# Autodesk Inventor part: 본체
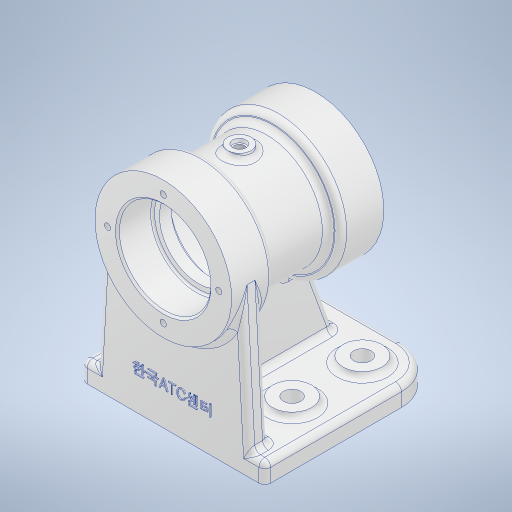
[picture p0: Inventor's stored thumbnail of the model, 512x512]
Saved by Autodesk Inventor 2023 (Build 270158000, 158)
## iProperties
Created: 2024-02
Part Number: 본체
Material: 알루미늄 6061
Document SubType Name: Modeling
Designer: home
Density: 2.7 g/cm^3
Appearance: 알루미늄 - 평지
Mass: 719.723 g
Surface Area: 647.2 cm^2
Volume: 266.564 cm^3
Author: home
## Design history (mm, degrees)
sketch "스케치1"
  geometry: L1 (-47, -5)-(47, -5); L2 (47, -5)-(47, 5); L3 (47, 5)-(-47, 5); L4 (-47, 5)-(-47, -5); L5 (-47, -5)-(47, 5); L6 (47, -5)-(-47, 5); 1 further point
  constraints: 12 end point, 2 midpoint, 2 parallel, 1 horizontal, 1 perpendicular
  dimensions: "d0" = 94 distance of L2.end L3.end; "d1" = 10 distance of L3.end L1.start
extrude "돌출1" new body sketch "스케치1" distance "d2" = 90; taper "d3" = 0 deg
node "작업 평면1"
sketch "스케치2"
  geometry: L1 (-47, -5)-(47, -5) reference; C1 r 35 at (0, 75); 1 further point
  constraints: 1 centre point, 1 vertical alignment
  dimensions: "d5" = 70 diameter of C1; "d6" = 80 distance from line of L1 C1.centre
extrude "돌출2" join sketch "스케치2" distance "d7" = 22; taper "d8" = 0 deg
sketch "스케치3"
  geometry: C1 r 35 at (0, 0) reference; C2 r 28.5 at (0, 0); 1 further point
  constraints: 1 centre point, 1 coincident
  dimensions: "d9" = 57 diameter of C2
extrude "돌출3" join sketch "스케치3" distance "d10" = 34; taper "d11" = 0 deg
sketch "스케치4"
  geometry: C1 r 28.5 at (0, 0) reference; C2 r 35 at (0, 0); 1 further point
  constraints: 1 centre point, 1 coincident
  dimensions: "d12" = 70 diameter of C2
extrude "돌출4" join sketch "스케치4" distance "d13" = 22; taper "d14" = 0 deg
sketch "스케치5"
  geometry: L1 (-47, 5)-(47, 5) reference; L2 (39, 5)-(34.945, 76.969); L3 (47, -5)-(47, 5) reference; L4 (0, 5)-(39, 5); L5 (34.945, 76.969)-(0, 56.544); L6 (0, 56.544)-(0, 5); 2 further points
  constraints: 8 end point, 1 collinear, 1 midpoint, 1 perpendicular, 1 point on line, 3 other
  dimensions: "d15" = 8 distance from line of L3 L2.start
extrude "돌출5" join sketch "스케치5" distance "d16" = 10; taper "d17" = 0 deg
sketch "스케치6"
  geometry: L1 (5, 0)-(5, -90) reference; L2 (5, -78)-(64.493, -56.346); L3 (64.493, -56.346)-(64.493, 0); L4 (5, 0)-(76.969, 0) reference; L5 (5, -90)-(-5, -90) reference; 2 further points
  constraints: 4 end point, 2 point on line, 1 coincident, 1 vertical
  dimensions: "d18" = 12 distance from line of L5 point (5, -78); "d19" = 70 deg angle of L2 L1
extrude "돌출6" join sketch "스케치6" stored distance "d20" = 10; taper "d21" = 0 deg
sketch "스케치7"
  geometry: L1 (40, -73)-(110, -73) reference; L2 (75, -73)-(75, 5); L3 (110, 5)-(40, 5) reference; L4 (110, 5)-(110, -17) reference; L5 (75, 5)-(98.5, 5); L6 (98.5, 5)-(98.5, -13); L7 (98.5, -13)-(75, -13); L8 (75, -13)-(75, 5); L9 (75, -13)-(95, -13); L10 (95, -13)-(95, -19); L11 (95, -19)-(75, -19); L12 (75, -19)-(75, -13); L13 (75, -19)-(98.5, -19); L14 (98.5, -19)-(98.5, -49); L15 (98.5, -49)-(75, -49); L16 (75, -49)-(75, -19); L17 (75, -49)-(95, -49); L18 (95, -49)-(95, -55); L19 (95, -55)-(75, -55); L20 (75, -55)-(75, -49); L21 (75, -55)-(98.5, -55); L22 (98.5, -55)-(98.5, -73); L23 (98.5, -73)-(75, -73); L24 (75, -73)-(75, -55); 6 further points
  constraints: 42 end point, 10 parallel, 5 horizontal, 5 perpendicular, 3 point on line, 2 midpoint
  dimensions: "d22" = 47 diameter of L6 L2; "d23" = 40 diameter of L10 L2; "d24" = 47 diameter of L14 L2; "d25" = 18 distance of L5.end L6.end; "d26" = 6 distance of L9.end L10.end; "d27" = 30 distance of L13.end L14.end; "d28" = 18 distance of L21.end L22.end
revolve "회전1" sketch "스케치7" stored, may be unused: angle "d29" = 90 deg
fillet "모깎기1" dims "d30" = 3
fillet "모깎기2" dims "d31" = 1
sketch "스케치8"
  geometry: C1 r 35 at (0, 0) reference; A1 r 28.5 centre (0, 0) between (-5, -28.058) and (5, -28.058); A2 r 28.5 centre (0, 0) between (5, -28.058) and (-5, -28.058) reference; 2 further points
  constraints: 1 centre point, 1 coincident, 1 point on circle
  dimensions: "d32" = 57 diameter of A1
hole "구멍1" sketch "스케치8" at (0, 28.5) diameter "d33" = 3.242; stored, may be unused: countersink angle "d37" = 90 deg, drill point angle "d39" = 118 deg; dims "d34" = 8, "d35" = 4, "d36" = 2, "d38" = 10
sketch "스케치9"
  geometry: C1 r 35 at (0, 0) reference; C2 r 28.5 at (0, 0); C3 r 1.621 at (0, 28.5) reference; 2 further points
  constraints: 2 coincident, 1 centre point
  dimensions: "d43" = 57 diameter of C2
hole "구멍2" sketch "스케치9" at (0, 28.5) diameter "d44" = 3.242; stored, may be unused: countersink angle "d48" = 90 deg, drill point angle "d50" = 118 deg; dims "d45" = 8, "d46" = 4, "d47" = 2, "d49" = 10
sketch "스케치10"
  geometry: L1 (8, -90)-(0, -90) reference; L2 (20, -20)-(74, -20); L3 (74, -20)-(74, -56); L4 (74, -56)-(20, -56); L5 (20, -56)-(20, -20); L6 (20, -20)-(74, -56); L7 (74, -20)-(20, -56); L8 (12, -90)-(82, -90) reference; C1 r 10 at (20, -20); C2 r 10 at (74, -20); C3 r 10 at (74, -56); C4 r 10 at (20, -56); 5 further points
  constraints: 12 end point, 4 centre point, 4 coincident, 3 midpoint, 2 parallel, 1 horizontal, 1 perpendicular, 1 vertical alignment
  dimensions: "d54" = 54 distance of L2.start L2.end; "d55" = 36 distance of L4.end L2.start; "d56" = 34 distance between parallel lines of L1 L4; "d57" = 20 diameter of C1; "d58" = 20 diameter of C2; "d59" = 20 diameter of C3; "d60" = 20 diameter of C4
extrude "돌출7" join sketch "스케치10" distance "d61" = 3; taper "d62" = 0 deg
sketch "스케치11"
  geometry: C1 r 10 at (0, 0) reference; C2 r 4.5 at (0, 0); 1 further point
  constraints: 1 centre point, 1 coincident
  dimensions: "d64" = 9 diameter of C2
extrude "돌출8" cut sketch "스케치11" extent not by distance; stored distance "d65" = 0; taper "d66" = 0 deg
sketch "스케치12"
  geometry: C1 r 10 at (0, 0) reference; C2 r 4.5 at (0, 0); 1 further point
  constraints: 1 centre point, 1 coincident
  dimensions: "d67" = 9 diameter of C2
extrude "돌출9" cut sketch "스케치12" extent not by distance; stored distance "d68" = 0; taper "d69" = 0 deg
fillet "모깎기3" dims "d70" = 20
fillet "모깎기4" dims "d71" = 3
fillet "모깎기5" dims "d72" = 3
fillet "모깎기6" dims "d73" = 3
fillet "모깎기7" dims "d74" = 3
fillet "모깎기8" dims "d75" = 3
node "작업 평면2"
sketch "스케치13"
  geometry: L1 (-3.489, 93)-(57.489, 93) reference; L2 (62, 95)-(-8, 95) reference; C1 r 6 at (27, 56); 2 further points
  constraints: 1 centre point, 1 midpoint, 1 vertical alignment
  dimensions: "d77" = 12 diameter of C1; "d78" = 39 distance from line of L2 C1.centre
extrude "돌출10" join sketch "스케치13" distance "d79" = 6.5; taper "d80" = 0 deg
sketch "스케치14"
  geometry: C1 r 6 at (0, 0) reference; 2 further points
  constraints: 1 coincident
hole "구멍3" sketch "스케치14" at (0, 0) diameter "d81" = 5.1881; stored, may be unused: countersink angle "d85" = 90 deg, drill point angle "d87" = 0 deg; dims "d82" = 12, "d83" = 7, "d84" = 2, "d86" = 16
fillet "모깎기9" dims "d88" = 3
chamfer "모따기1" distance "d89" = 1; stored, may be unused: second distance "d90" = 2, angle "d91" = 45 deg
fillet "모깎기10" dims "d92" = 3
sketch "스케치15"
  geometry: L1 (-44, -5)-(44, -5) reference; 2 further points
  constraints: 1 vertical alignment, 1 other
  dimensions: "d93" = 20 distance from line of L1 point (0, 15)
feature "엠보싱1" sketch "스케치15" dims "d94" = 0.5, "d95" = 0
node "솔리드1"
mirror "미러1"
pattern_circular "원형 패턴1" dims angle "d41" = 360 deg
pattern_circular "원형 패턴2" dims angle "d52" = 360 deg
mirror "미러2"
mirror "미러3"
feature "A9D066F2-1C7D-4E18-AEED-F7BC21143FA4" dims "d44" = 3.242, "d45" = 8, "d46" = 4, "d47" = 2, "d48" = 90 deg, "d49" = 10, "d50" = 118 deg
other parameters: "d4" = 5, "d76" = -111.5
